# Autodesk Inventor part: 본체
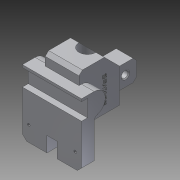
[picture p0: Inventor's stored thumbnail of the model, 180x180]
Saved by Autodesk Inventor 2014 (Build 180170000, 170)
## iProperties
Created: 2016-11
Part Number: 본체
Material: 알루미늄 6061
Document SubType Name: Modeling
Designer: owner
Density: 2.71 g/cm^3
Appearance: 알루미늄 - 평지
Mass: 473.131 g
Surface Area: 322.106 cm^2
Volume: 174.587 cm^3
Author: owner
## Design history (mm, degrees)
sketch "스케치1"
  geometry: L1 (0, 13)-(-15, 13); L2 (-15, 13)-(-15, 10); L3 (-15, 10)-(-8, 10); L4 (-8, 10)-(-8, -10); L5 (-8, -10)-(-15, -10); L6 (-15, -10)-(-15, -63); L7 (-15, -63)-(0, -63); L8 (0, -63)-(0, -13); L9 (-3, 27)-(27, 27); L10 (27, 27)-(45, 9); L11 (45, 9)-(45, -1); L12 (45, -1)-(75, -1); L13 (75, -1)-(75, -26); L14 (75, -26)-(45, -26); L15 (45, -26)-(45, -31); L16 (45, -31)-(5, -31); L17 (5, -31)-(5, -63); L18 (5, -63)-(0, -63); L19 (45, -26)-(45, -1); L20 (-3, 27)-(-3, 13); A1 r 13 centre (0, 0) between (0, -13) and (0, 13); 2 further points
  constraints: 40 end point, 9 parallel, 5 perpendicular, 3 collinear, 3 point on line, 2 point on circle, 1 centre point, 1 coincident, 1 horizontal, 1 tangent
  dimensions: "d1" = 13 radius of A1; "d2" = 15 distance between parallel lines of L6 L8; "d3" = 7 distance of L2.end L3.end; "d4" = 3 distance of L1.end L2.end; "d6" = 20 distance of L3.end L4.end; "d7" = 63 distance from line of point (0, 0) L7; "d8" = 18 distance from line of L9 L10.end; "d9" = 45 deg angle of L9 L10; "d12" = 58 distance between parallel lines of L16 L9; "d13" = 25 distance of L12.end L13.end; "d14" = 5 distance of L14.end L15.end; "d15" = 90 distance between parallel lines of L18 L9; "d16" = 20 distance between parallel lines of L6 L17; "d17" = 90 distance between parallel lines of L6 L13; "d66" = 30 distance from line of L20 L9.end; "d67" = 60 distance between parallel lines of L6 L11
extrude "돌출1" new body sketch "스케치1" stored distance "d18" = 70; taper "d19" = 0 deg
extrude "돌출2" join sketch "스케치1" stored distance "d20" = 40; taper "d21" = 0 deg
extrude "돌출3" join sketch "스케치1" stored distance "d22" = 20; taper "d23" = 0 deg
sketch "스케치2"
  geometry: L1 (40, 0)-(0, 0) reference; L2 (55, -60)-(-15, -60) reference; 3 further points
  constraints: 1 midpoint, 1 vertical alignment
  dimensions: "d24" = 42 distance from line of L2 point (20, -18)
hole "구멍1" sketch "스케치2" at (20, -18) diameter "d25" = 20; stored, may be unused: countersink angle "d29" = 90 deg, drill point angle "d31" = 118 deg; dims "d26" = 6, "d27" = 29, "d28" = 7, "d30" = 8
sketch "스케치3"
  geometry: L1 (55, 20)-(15, 20) reference; L2 (70, 0)-(0, 0) reference; L3 (70, 15)-(70, 0) reference; L4 (35, 15)-(35, -0.983); L5 (41, 0)-(41, 13.627); L6 (29, 0)-(29, 13.627); C1 r 14.5 at (35, 42) reference; A1 r 29 centre (35, 42) between (16.106, 20) and (29, 13.627); A2 r 29 centre (35, 42) between (41, 13.627) and (53.894, 20)
  constraints: 6 end point, 4 point on circle, 4 point on line, 3 parallel, 2 centre point, 1 coincident, 1 concentric, 1 other
  dimensions: "d34" = 12 distance between parallel lines of L6 L5; "d35" = 29 radius of A2
extrude "돌출4" cut sketch "스케치3" distance "d36" = 18; taper "d37" = 0 deg
sketch "스케치4"
  geometry: L1 (-15, 50)-(0, 50) reference; L2 (-25, -40)-(-45, -40) reference; L3 (-16.106, 32)-(-53.894, 32) reference; L4 (-35, -40)-(-35, 32); 5 further points
  constraints: 2 end point, 2 midpoint, 1 symmetric about line
  dimensions: "d38" = 18 distance from line of L1 point (-7.5, 32); "d39" = 55 diameter of point (-7.5, 32) L4
hole "구멍2" sketch "스케치4" at (-7.5, 32), (-62.5, 32) diameter "d40" = 3.242; stored, may be unused: countersink angle "d44" = 90 deg, drill point angle "d46" = 118 deg; dims "d41" = 6, "d42" = 29, "d43" = 7, "d45" = 8
sketch "스케치5"
  geometry: L1 (26, 75)-(1, 75) reference; L2 (10, -15)-(63, -15) reference; C1 r 4 at (13.5, 62); 2 further points
  constraints: 1 centre point, 1 midpoint, 1 vertical alignment
  dimensions: "d47" = 77 distance from line of L2 C1.centre; "d48" = 8 diameter of C1
extrude "돌출5" cut sketch "스케치5" stored distance "d49" = 18; taper "d50" = 0 deg
sketch "스케치6"
  geometry: L1 (31, 5)-(31, 45) reference; L2 (31, 45)-(-9, 45) reference; 1 further point
  constraints: 1 other
  dimensions: "d51" = 25 distance from line of L1 point (6, 27); "d52" = 18 distance from line of L2 point (6, 27)
feature "엠보싱1" sketch "스케치6" dims "d1" = 13, "d2" = 15, "d3" = 7, "d4" = 3, "d6" = 20, "d7" = 63, "d8" = 18, "d9" = 45 deg, "d12" = 58, "d13" = 25, "d14" = 5, "d15" = 90, "d16" = 20, "d17" = 90, "d20" = 40, "d53" = 0.5, "d54" = 0, "d66" = 30, "d67" = 60
chamfer "모따기1" distance "d55" = 1; stored, may be unused: second distance "d56" = 2, angle "d57" = 45 deg
chamfer "모따기2" distance "d58" = 4; stored, may be unused: second distance "d59" = 2, angle "d60" = 45 deg
fillet "모깎기1" dims "d61" = 5
fillet "모깎기2" dims "d62" = 3
chamfer "모따기3" distance "d63" = 5; stored, may be unused: second distance "d64" = 2, angle "d65" = 45 deg
node "솔리드1"
other parameters: "d33" = 29
